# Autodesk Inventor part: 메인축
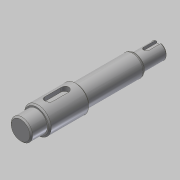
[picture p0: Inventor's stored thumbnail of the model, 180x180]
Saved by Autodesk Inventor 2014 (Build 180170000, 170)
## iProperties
Created: 2019-03
Part Number: 메인축
Material: 강철, 연강
Document SubType Name: Modeling
Designer: mduedu
Density: 1 g/cm^3
Appearance: 강철
Author: mduedu
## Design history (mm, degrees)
sketch "스케치1"
  geometry: L1 (0, 0)-(12, 0); L2 (12, 0)-(12, 8); L3 (12, 8)-(0, 8); L4 (0, 8)-(0, 0); L5 (12, 0)-(42, 0); L6 (42, 0)-(42, 10); L7 (42, 10)-(12, 10); L8 (12, 10)-(12, 0); L9 (42, 0)-(86, 0); L10 (86, 0)-(86, 8); L11 (86, 8)-(42, 8); L12 (42, 8)-(42, 0); L13 (86, 0)-(104, 0); L14 (104, 0)-(104, 6); L15 (104, 6)-(86, 6); L16 (86, 6)-(86, 0)
  constraints: 32 end point, 8 parallel, 4 horizontal, 4 perpendicular
  dimensions: "d0" = 16 diameter of L3 L1; "d2" = 20 diameter of L7 L5; "d3" = 16 diameter of L11 L9; "d4" = 12 diameter of L15 L13; "d5" = 12 distance of L2.end L3.end; "d6" = 30 distance of L6.end L7.end; "d7" = 86 distance between parallel lines of L10 L4; "d8" = 104 distance between parallel lines of L14 L4
revolve "회전1" sketch "스케치1" stored, may be unused: angle "d9" = 90 deg
node "작업 평면1"
sketch "스케치2" dims "d10" = 18
  geometry: L1 (6, -3)-(-6, -3); L2 (-6, -3)-(-6, 3); L3 (-6, 3)-(6, 3); L4 (6, 3)-(6, -3); L5 (15, 10)-(15, -10) reference; 3 further points
  constraints: 8 end point, 2 midpoint, 2 parallel, 2 vertical alignment, 1 horizontal, 1 horizontal alignment, 1 perpendicular, 4 other
  dimensions: "d12" = 6 distance between parallel lines of L3 L1; "d13" = 6 dimension on L5
extrude "돌출1" cut sketch "스케치2" distance "d14" = 3.5; taper "d15" = 0 deg
node "작업 평면2"
sketch "스케치3"
  geometry: L1 (-9, 6)-(-9, -6) reference; L2 (1, -2)-(-9, -2); L3 (1, 2)-(-9, 2); A1 r 2 centre (1, 0) between (1, -2) and (1, 2); 2 further points
  constraints: 4 end point, 2 point on circle, 2 point on line, 2 tangent, 1 centre point, 1 horizontal alignment, 1 midpoint, 1 parallel, 1 perpendicular
  dimensions: "d16" = 12 dimension on A1 L1; "d17" = 4 distance between parallel lines of L3 L2
extrude "돌출2" cut sketch "스케치3" distance "d18" = 2.5; taper "d19" = 0 deg
chamfer "모따기1" distance "d20" = 1; stored, may be unused: second distance "d21" = 2, angle "d22" = 45 deg
chamfer "모따기2" distance "d23" = 1; stored, may be unused: second distance "d24" = 2, angle "d25" = 45 deg
chamfer "모따기3" distance "d26" = 1.73; stored, may be unused: second distance "d27" = 2, angle "d28" = 30 deg
fillet "모깎기2" dims "d31" = 1, "d32" = 2
node "솔리드1"
